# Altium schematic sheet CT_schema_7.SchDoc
size 371 x 335 mm
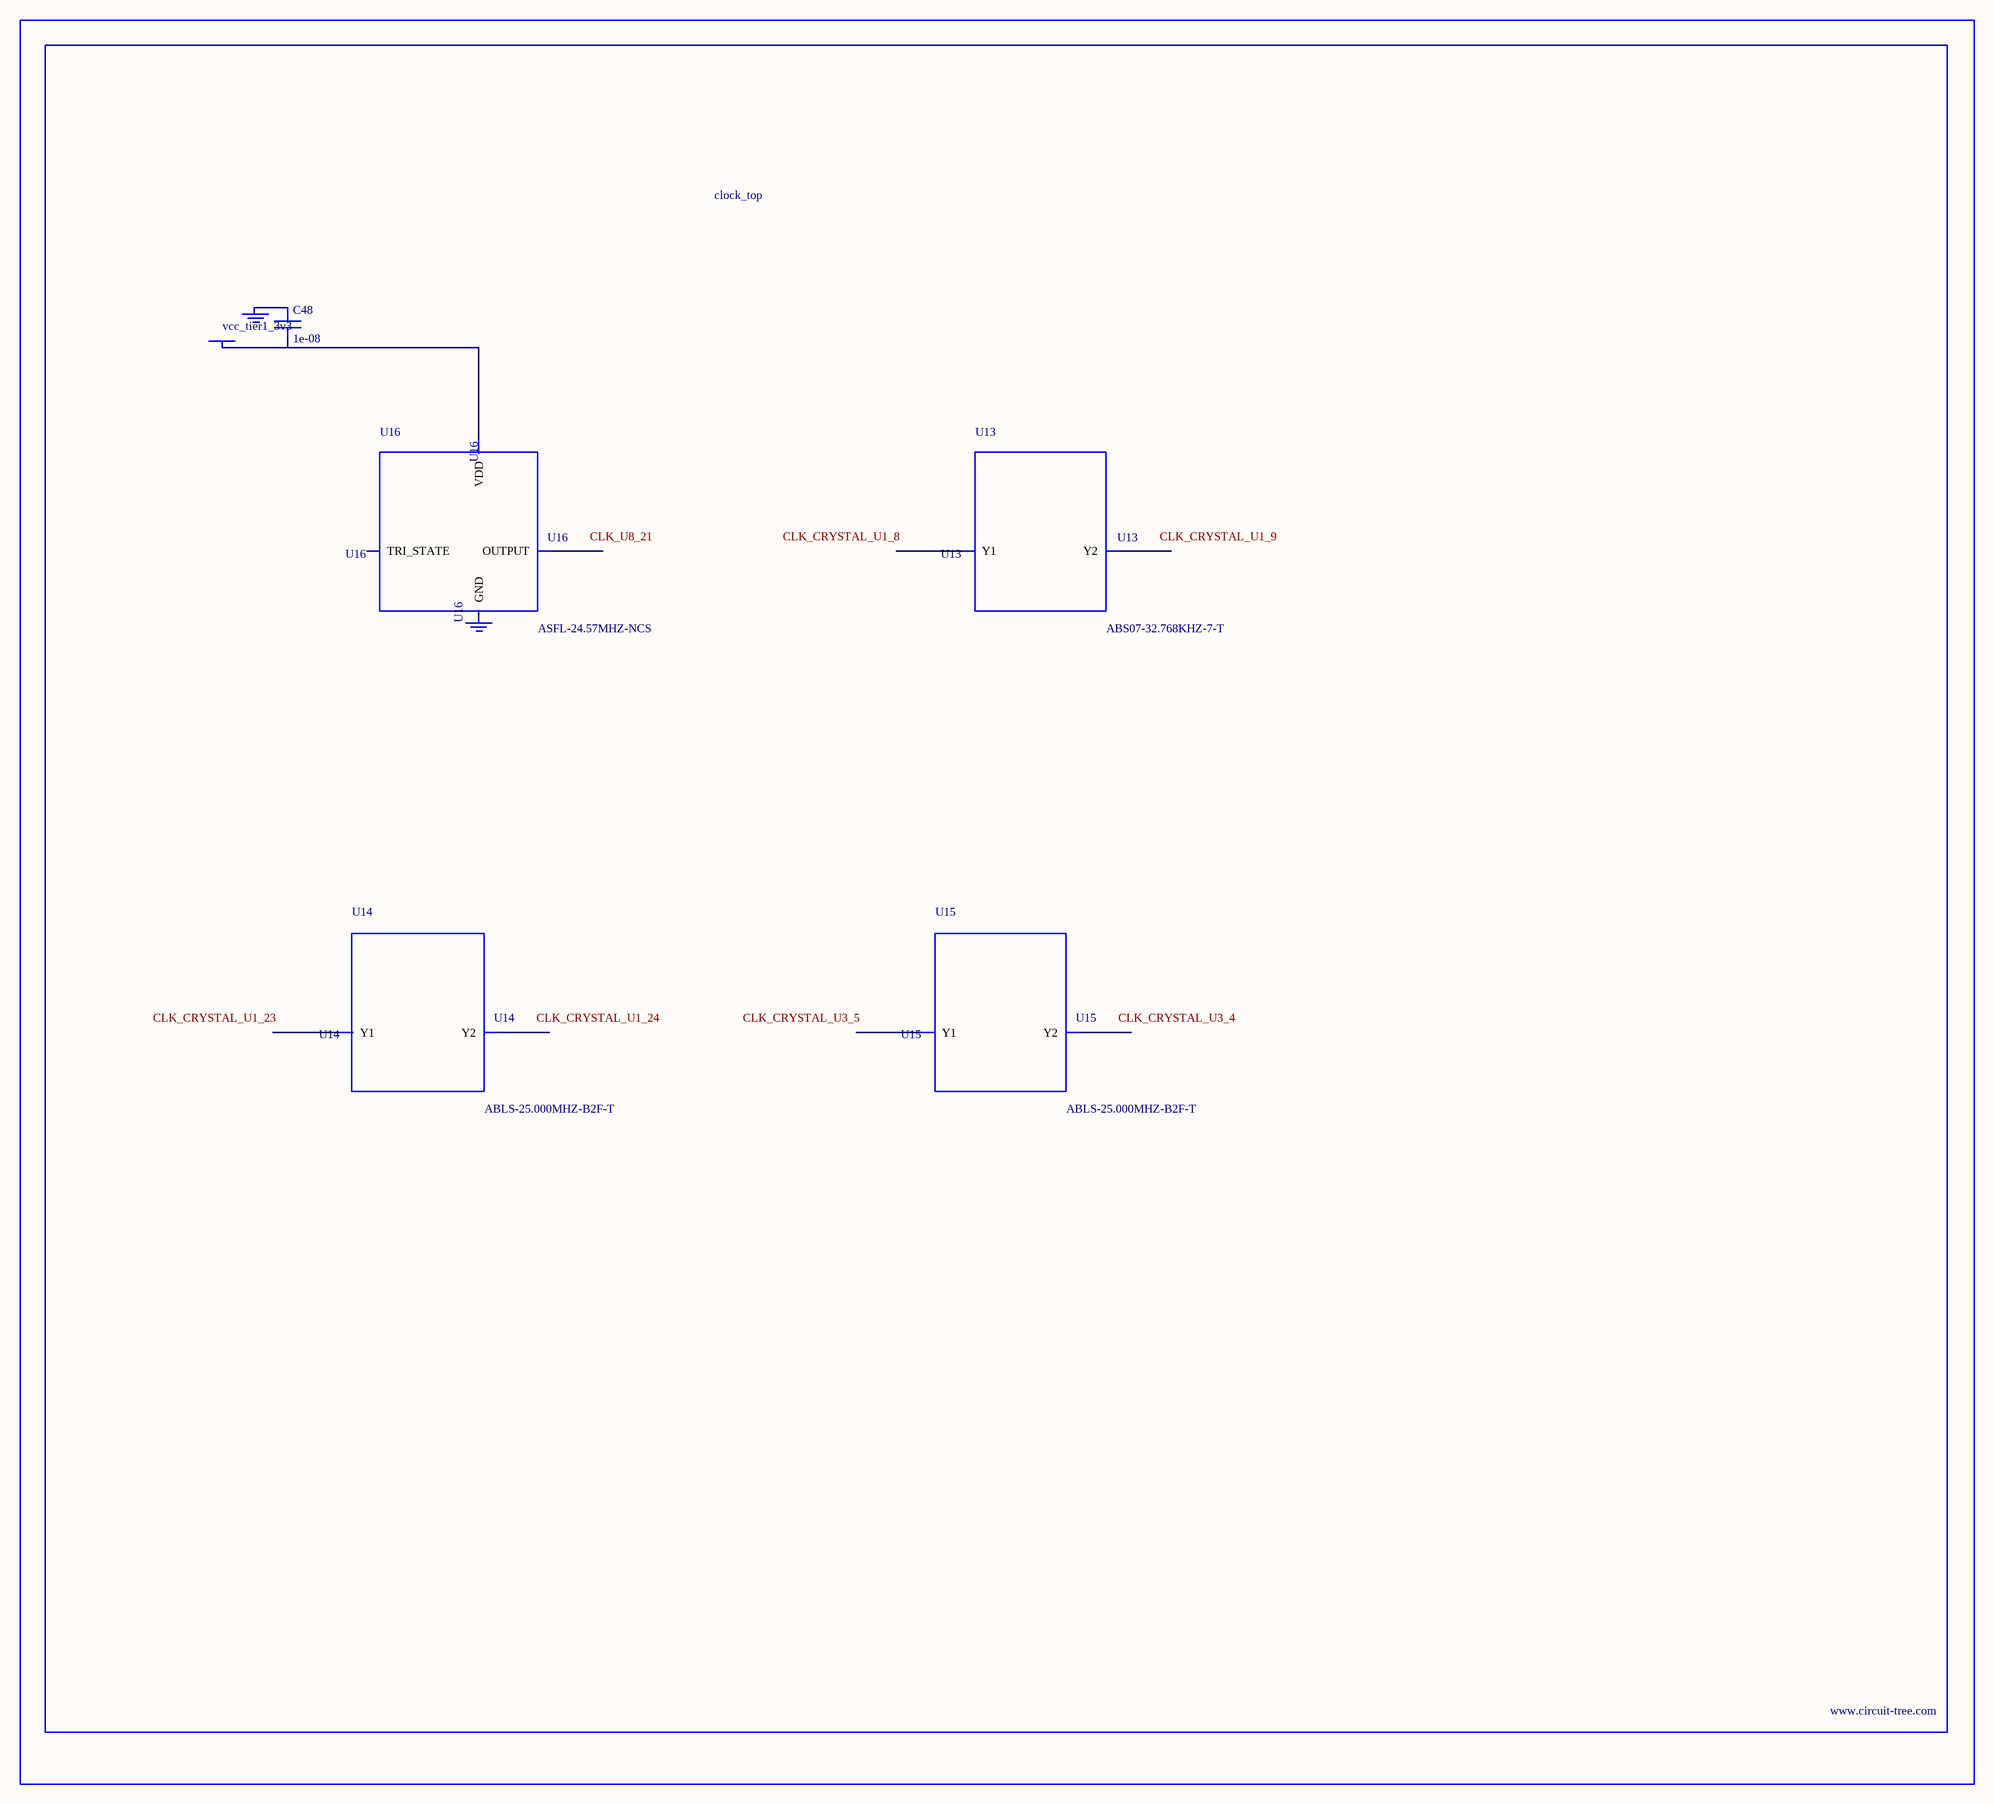
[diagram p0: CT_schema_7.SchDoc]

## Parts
BORDER6  (no value)
C48  1e-08  [C0402]
GND_INSTANCE_6_0  (no value)
GND_INSTANCE_6_1  (no value)
POWER_INSTANCE_6_0  vcc_tier1_3v3
U13  ABS07-32.768KHZ-7-T  [ABS07-32.768KHZ-7-T]
U14  ABLS-25.000MHZ-B2F-T  [ABLS-25.000MHZ-B2F-T]
U15  ABLS-25.000MHZ-B2F-T  [ABLS-25.000MHZ-B2F-T]
U16  ASFL-24.57MHZ-NCS  [ASFL1]

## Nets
NetC48_1: C48.1 GND_INSTANCE_6_0.0(GND)
NetC48_2: C48.2 POWER_INSTANCE_6_0.0(PWR) U16.4(VDD)

Not connected (* = marked no-connect by the designer): GND_INSTANCE_6_1 0(GND); U13 1(Y1) 2(Y2); U14 1(Y1) 2(Y2); U15 1(Y1) 2(Y2); U16 1(TRI_STATE) 2(GND) 3(OUTPUT)

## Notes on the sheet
- Labels drawn without touching a wire or pin: CLK_CRYSTAL_U1_8, CLK_CRYSTAL_U1_9, CLK_CRYSTAL_U1_23, CLK_CRYSTAL_U1_24, CLK_CRYSTAL_U3_4, CLK_CRYSTAL_U3_5, CLK_U8_21

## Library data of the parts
BORDER6 = BORDER_PAGE6
C48 = C0402C103K3RAC
GND_INSTANCE_6_0 GND_INSTANCE_6_1 = GND
POWER_INSTANCE_6_0 = PWR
